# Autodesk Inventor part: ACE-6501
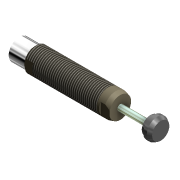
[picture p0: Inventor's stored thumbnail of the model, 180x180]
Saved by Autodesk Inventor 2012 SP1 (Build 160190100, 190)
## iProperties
Shininess: 0.0
Length Units: 11272
Angle Units: 11279
Time Units: 11290
Mass Units: 11283
Length Display Precision: 3
Angle Display Precision: 2
Compacted: True
Created: 2000-06
Part Number: ACE-6501
Description: SHOCK ABSORBER
Vendor: REID TOOL
Document SubType Name: Modeling
Designer: Ron
Density: 1 g/cm^3
Material: Default
Density: 0.0
Volumn: 0.0
Area: 0.0
PropertySet Name: Model Information
Control State: 0
Master: False
Checked Out: False
Title: SHOCK ABSORBER
Author: Ron
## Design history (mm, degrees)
node "RevolutionAngle1" dims "d0" = 360 deg
  sketch "Sketch1"
    geometry: L1 (-71.374, 11.176)-(-71.374, 0); L2 (-54.787, 11.176)-(-71.374, 11.176); L3 (-53.301, 12.662)-(-54.787, 11.176); L4 (35.091, 12.662)-(-53.301, 12.662); L5 (35.091, 3.137)-(35.091, 12.662); L6 (66.841, 3.137)-(35.091, 3.137); L7 (66.841, 9.106)-(66.841, 3.137); L8 (70.499, 9.106)-(66.841, 9.106); L9 (70.499, 11.176)-(70.499, 9.106); L10 (74.138, 11.176)-(70.499, 11.176); L11 (77.724, 9.106)-(74.138, 11.176); L12 (77.724, 0)-(77.724, 9.106); L13 (-71.374, 0)-(77.724, 0); 1 further point
    constraints: 28 end point, 5 horizontal, 5 vertical, 1 collinear, 1 perpendicular, 1 point on line, 1 other
    dimensions: "d7" = 22.352 diameter of L2 L13; "d8" = 25.3238 diameter of L4 L13; "d9" = 18.2118 diameter of L8 L13; "d10" = 6.2738 diameter of L6 L13; "d11" = 106.46511 distance between parallel lines of L5 L1; "d12" = 10.88289 distance between parallel lines of L12 L7; "d13" = 3.6576 distance of L8.start L7.start; "d14" = 60 deg angle of L12 L11; "d15" = 31.75 distance of L6.start L5.start; "d16" = 45 deg angle of L4 L3; "d17" = 18.07311 distance from line of L1 L3.start
workplane "Work Plane1"
sketch "Sketch3"
  geometry: L1 (11.176, -5.224)-(11.176, -17.128); C1 r 11.176 at (0, -11.176) reference; C2 r 11.176 at (0, -11.176) reference; A1 r 12.662 centre (0, -11.176) between (11.176, -5.224) and (11.176, -17.128) reference
  constraints: 2 end point, 2 point on circle, 1 tangent, 1 vertical
extrude "Extrusion2" cut sketch "Sketch3" distance "d18" = 9.525; taper "d19" = 0 deg
mirror "Mirror1"
workplane "Work Plane2"
mirror "Mirror2"
chamfer "Chamfer1" distance "d20" = 1.27; stored, may be unused: second distance "d21" = 3.175, angle "d22" = 75 deg
thread "Thread2" dims "d25" = 76.2, "d26" = 0
body "Solid1"
